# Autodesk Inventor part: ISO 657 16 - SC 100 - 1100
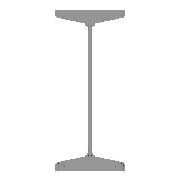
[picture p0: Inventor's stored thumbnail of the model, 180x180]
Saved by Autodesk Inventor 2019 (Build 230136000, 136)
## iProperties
_CCFamilyMember: 1
_CCFamilyDisplayName: ISO 657/16 - 1980 - Poutres en acier laminées à chaud - Partie 16: profilés en H (série métrique) - Cotes et propriétés de section
_FrameMemberDoc: Frame Member File
_Version: 15.0.0
_GetPNFromCC: 1
Created: 2018-07
Part Number: ISO 657 16 - SC 100 - 1100
Material: Acier, doux
Description: Poutres en acier laminées à chaud - Partie 16: profilés en H (série métrique) - Cotes et propriétés de section
Document SubType Name: Modeling
Standard: ISO
Designer: Fabian Perrée
Standard Revision: First edition 1980-02-15
Standards Organization: ISO
Language: fr-FR
Size Designation: SC 100
Categories: <MemberInstance><Categories><Category DisplayName="Profilés" InternalName="089c4875-fa83-4c05-b084-43b9cc11f5ed" Mnemonic="GRDR"><CategoryParameter DisplayName=
Stock Number: SC 100
Density: 7.85 g/cm^3
Appearance: Semi-poli
Mass: 21988.2 g
Surface Area: 6005.15 cm^2
Volume: 2801.04 cm^3
IsCustomPart: 1
G_W: 100,000 mm
G_H: 100,000 mm
G_L: 1100,000 mm
+4F52C2C1-A5DF-49FF-BCF2-1C6DCEAB31C4+DETAILDECOUPE3: Angle de coupe 90,00 deg
+F238D13F-B22F-435D-A7DE-D58E724D498D+DETAILDECOUPE4: Angle de coupe 90,00 deg
Author: Fabian Perrée
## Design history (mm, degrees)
node "Plan de départ"
node "Plan de fin"
sketch "Esquisse"
  geometry: L1 (-3, 0)-(-3, -26.266); L2 (-13.33, -38.149)-(-44.835, -42.577); L3 (-50, -48.518)-(-50, -50); L4 (-50, -50)-(0, -50); L5 (-26.5, -50)-(-26.5, -40); L6 (-61.333, 0)-(81.777, 0); L7 (0, 0)-(0, -50); L8 (0, -60)-(0, 80); L9 (3, 0)-(3, -26.266); L10 (13.33, -38.149)-(44.835, -42.577); L11 (50, -48.518)-(50, -50); L12 (50, -50)-(0, -50); L13 (-3, 0)-(0, 0); L14 (-3, 0)-(-3, 26.266); L15 (-13.33, 38.149)-(-44.835, 42.577); L16 (-50, 48.518)-(-50, 50); L17 (-50, 50)-(0, 50); L18 (50, 48.518)-(50, 50); L19 (13.33, 38.149)-(44.835, 42.577); L20 (3, 0)-(3, 26.266); L21 (50, 50)-(0, 50); L22 (0, 108)-(0, -88) reference; L23 (-89.955, 0)-(110.399, 0) reference; A1 r 6 centre (-44, 48.518) between (-50, 48.518) and (-44.835, 42.577); A2 r 6 centre (44, 48.518) between (44.835, 42.577) and (50, 48.518); A3 r 6 centre (44, -48.518) between (50, -48.518) and (44.835, -42.577); A4 r 6 centre (-44, -48.518) between (-44.835, -42.577) and (-50, -48.518); A5 r 12 centre (-15, 26.266) between (-3, 26.266) and (-13.33, 38.149); A6 r 12 centre (15, 26.266) between (13.33, 38.149) and (3, 26.266); A7 r 12 centre (15, -26.266) between (3, -26.266) and (13.33, -38.149); A8 r 12 centre (-15, -26.266) between (-13.33, -38.149) and (-3, -26.266); 14 further points
  constraints: 42 end point, 24 point on line, 17 symmetric about line, 16 point on circle, 16 tangent, 8 centre point, 6 equal radius, 4 collinear, 2 perpendicular, 12 other
  dimensions: "d1" = 10 vertical distance of L3.end L5.end (= G_T1); "d2" = 23.5 distance between parallel lines of L5 L3 (= -0.25 x G_T + 0.25 x G_W); "d3" = 3 distance between parallel lines of L1 L7 (= 0.5 x G_T); "d4" = 50 distance between parallel lines of L7 L3 (= 0.5 x G_W); "d9" = 50 distance from line of L1.start L4 (= 0.5 x G_H); "d14" = 98 deg angle of L2 L1 (= G_NG); "d15" = 6 radius of A1 (= G_ER); "d16" = 12 radius of A5 (= G_IR)
extrude "Corps" new body sketch "Esquisse" stored distance "d5" = 1100 (= G_L); taper "d6" = 0 deg
node "Driven Length"
  sketch "Sketch3"
    geometry: L1 (0, 0)-(10, 0) reference
    constraints: 2 end point, 1 horizontal
  workplane "Work Plane3"
  sketch "Sketch4"
    geometry: L1 (-2, -50)-(12, -50) reference; L2 (-2, 1050)-(12, 1050) reference
    dimensions: "d20" = 1100 distance between parallel lines of L1 L2 (derived)
node "Plan de construction8"
feature "Scission5"
node "Plan de construction9"
feature "Scission6"
body "Solid1"
other parameters: "G_W" = 100 (= G_H) [user parameter; used in 2 equation terms], "G_H" = 100 [user parameter; used in 2 equation terms], "G_T" = 6 [user parameter; used in 2 equation terms], "G_T1" = 10 [user parameter; used in 1 equation term], "G_L" = 1100 (= d20) [user parameter; used in 1 equation term], "G_ER" = 6 [user parameter; used in 1 equation term], "G_IR" = 12 [user parameter; used in 1 equation term], "G_NG" = 98 deg [user parameter; used in 1 equation term], "d19" = 90 deg
